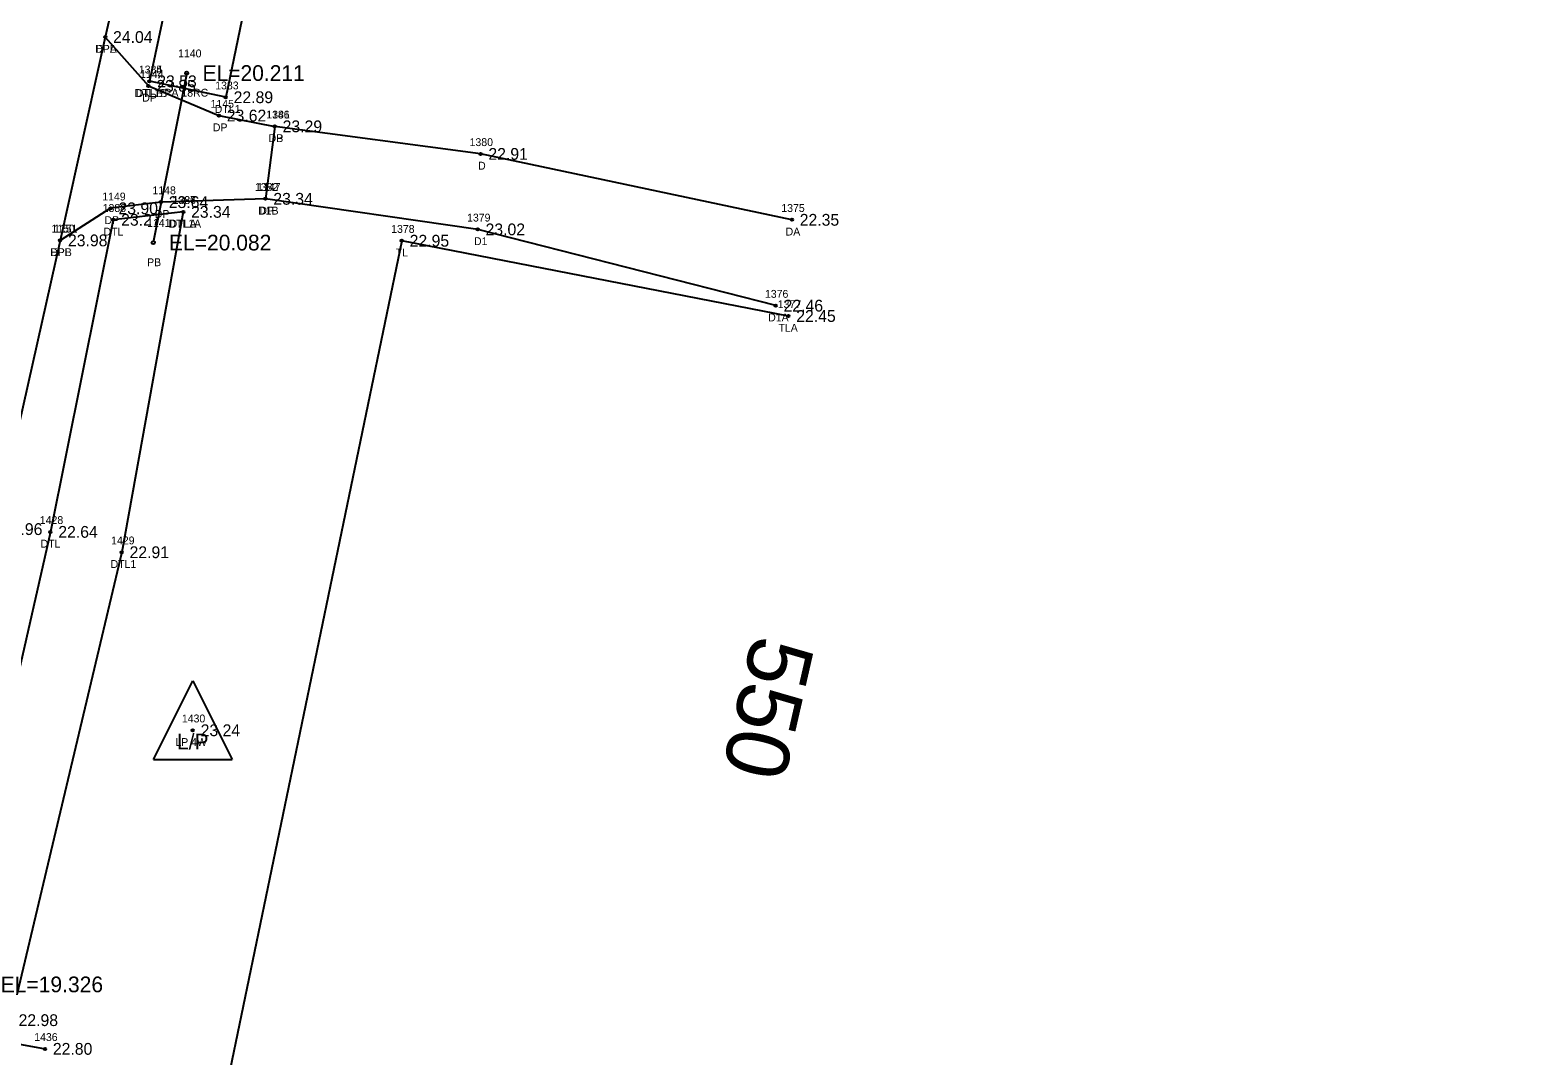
# Model space of a CAD drawing. Extents: x 2654414 to 2656963, y 761776 to 764965.
# Drawn here: x 2655871.2 to 2656062.9, y 763790 to 763920.5 of the extents above; entities that cross this region are included whole.
import ezdxf

# ---------------------------------------------------------------- set-up
doc = ezdxf.new("R2010")
doc.units = 0
for name, color, linetype in [('RD_EX_DR_Pipe', 7, 'Continuous'), ('RD_EX_DR_Pipe_txCode', 7, 'Continuous'), ('RD_EX_Driveway', 7, 'Continuous'), ('RD_EX_Driveway_txCode', 7, 'Continuous'), ('RD_EX_H2O', 7, 'Continuous'), ('RD_EX_H2O_txCode', 7, 'Continuous'), ('RD_EX_Road', 7, 'Continuous'), ('RD_EX_Road_txCode', 7, 'Continuous'), ('RD_EX_TX_Driveway_ELEV', 7, 'Continuous'), ('RD_EX_TX_H2O_ELEV', 7, 'Continuous'), ('RD_EX_TX_Road_ELEV', 7, 'Continuous'), ('RD_EX_TX_UT_ELEV', 7, 'Continuous'), ('RD_EX_TX_VEG_ELEV', 7, 'Continuous'), ('RD_EX_UT', 7, 'Continuous'), ('RD_EX_UT_txCode', 7, 'Continuous'), ('RD_EX_VEG', 7, 'Continuous'), ('RD_EX_VEG_txCode', 7, 'Continuous'), ('RD_HC_TX_Sta50', 7, 'Continuous'), ('RD_SMD_Locator', 7, 'Continuous'), ('RD_TX_Pipe_ElevEX', 7, 'Continuous')]:
    doc.layers.add(name, color=color, linetype=linetype)

msp = doc.modelspace()

# ---------------------------------------------------------------- linework, layer by layer
at = {"layer": 'RD_EX_DR_Pipe'}
msp.add_line((2655891.1, 763915.02), (2655886.84, 763893.45), dxfattribs=at)
at = {"layer": 'RD_EX_Driveway'}
for points in [[(2655880.73, 763919.6), (2655886.23, 763913.39), (2655895.19, 763909.61), (2655902.29, 763908.24), (2655901.11, 763899.02), (2655887.81, 763898.6), (2655881.42, 763897.81), (2655875, 763893.73)], [(2655968.03, 763896.35), (2655928.45, 763904.73), (2655902.29, 763908.24)], [(2655965.98, 763885.43), (2655928.09, 763895.13), (2655901.11, 763899.02)], [(2655852.89, 763796.34), (2655861.47, 763793.02), (2655873.08, 763790.88)]]:
    msp.add_lwpolyline(points, dxfattribs=at)
at = {"layer": 'RD_EX_H2O'}
msp.add_line((2655907.16, 764011.39), (2655886.35, 763913.97), dxfattribs=at)
for points in [[(2655907.16, 764011.39), (2655919.27, 764009.98), (2655903.67, 763948.66), (2655896.06, 763911.94), (2655886.35, 763913.97)], [(2655890.65, 763897.36), (2655882.83, 763854.06), (2655868.72, 763794.53), (2655860.12, 763796.62)], [(2655890.65, 763897.36), (2655881.76, 763896.35), (2655873.77, 763856.65), (2655860.12, 763796.62)]]:
    msp.add_lwpolyline(points, dxfattribs=at)
at = {"layer": 'RD_EX_Road'}
msp.add_lwpolyline([(2656062.87, 764717.57), (2656039.84, 764617.04), (2656035.41, 764597.94), (2656033.38, 764589.18), (2656018.27, 764522.6), (2656017.22, 764517.64), (2656011.07, 764490.22), (2655996.52, 764425.63), (2655974.03, 764327.02), (2655960.71, 764269.34), (2655951.96, 764231.59), (2655930.84, 764138.62), (2655926.81, 764121.01), (2655909.26, 764045.26), (2655908.15, 764039.87), (2655902.08, 764013.51), (2655888.19, 763952.26), (2655880.73, 763919.6), (2655875, 763893.73), (2655866.73, 763857), (2655852.89, 763796.34), (2655850.73, 763786.52)], dxfattribs=at)
at = {"layer": 'RD_EX_UT'}
for p, q in [((2655886.87, 763827.69), (2655891.87, 763837.69)), ((2655891.87, 763837.69), (2655896.87, 763827.69)), ((2655886.87, 763827.69), (2655896.87, 763827.69))]:
    msp.add_line(p, q, dxfattribs=at)
at = {"layer": 'RD_EX_VEG'}
msp.add_lwpolyline([(2655967.59, 763884.11), (2655918.44, 763893.69), (2655891.07, 763761.52), (2655804.95, 763371.58), (2655783.26, 763268.33)], dxfattribs=at)
at = {"layer": 'RD_SMD_Locator'}
for centre, radius in [((2655880.73, 763919.6), 0.15), ((2655880.73, 763919.6), 0.15), ((2655886.23, 763913.39), 0.15), ((2655886.35, 763913.97), 0.15), ((2655886.35, 763913.97), 0.15), ((2655891.1, 763915.02), 0.2), ((2655896.06, 763911.94), 0.15), ((2655895.19, 763909.61), 0.15), ((2655902.29, 763908.24), 0.15), ((2655902.29, 763908.24), 0.15), ((2655928.45, 763904.73), 0.15), ((2655887.81, 763898.6), 0.15), ((2655901.11, 763899.02), 0.15), ((2655901.11, 763899.02), 0.15), ((2655881.42, 763897.81), 0.15), ((2655881.76, 763896.35), 0.15), ((2655890.65, 763897.36), 0.15), ((2655890.65, 763897.36), 0.15), ((2655968.03, 763896.35), 0.15), ((2655928.09, 763895.13), 0.15), ((2655875, 763893.73), 0.15), ((2655875, 763893.73), 0.15), ((2655886.84, 763893.45), 0.2), ((2655918.44, 763893.69), 0.15), ((2655965.98, 763885.43), 0.15), ((2655967.59, 763884.11), 0.15), ((2655873.77, 763856.65), 0.15), ((2655882.83, 763854.06), 0.15), ((2655891.87, 763831.41), 0.15), ((2655873.08, 763790.88), 0.15)]:
    msp.add_circle(centre, radius, dxfattribs=at)

# ---------------------------------------------------------------- texts
at = {"layer": 'RD_EX_DR_Pipe_txCode'}
for s, p in [('1140', (2655890, 763917.02)), ('PA 18RC', (2655888.26, 763912.02)), ('1141', (2655886.06, 763895.45)), ('PB', (2655886.06, 763890.45))]:
    msp.add_text(s, height=1, dxfattribs=at).set_placement(p)
at = {"layer": 'RD_EX_Driveway_txCode'}
for s, p in [('DPA', (2655879.46, 763917.6)), ('1144', (2655885.17, 763914.39)), ('DP', (2655885.45, 763911.39)), ('1145', (2655894.13, 763910.61)), ('1146', (2655901.2, 763909.24)), ('1381', (2655901.22, 763909.24)), ('DP', (2655894.42, 763907.61)), ('DP', (2655901.51, 763906.24)), ('DB', (2655901.51, 763906.24)), ('1380', (2655927.06, 763905.73)), ('D', (2655928.14, 763902.73)), ('1148', (2655886.74, 763899.6)), ('1382', (2655899.77, 763900.02)), ('1147', (2655900.05, 763900.02)), ('1149', (2655880.36, 763898.81)), ('1375', (2655966.69, 763897.35)), ('DP', (2655880.64, 763895.81)), ('DP', (2655887.03, 763896.6)), ('D1B', (2655900.17, 763897.02)), ('DP', (2655900.33, 763897.02)), ('1379', (2655926.74, 763896.13)), ('1150', (2655873.89, 763894.73)), ('DA', (2655967.24, 763894.35)), ('DPB', (2655873.74, 763891.73)), ('D1', (2655927.62, 763893.13)), ('1376', (2655964.61, 763886.43)), ('D1A', (2655965.02, 763883.43)), ('1436', (2655871.71, 763791.88))]:
    msp.add_text(s, height=1, dxfattribs=at).set_placement(p)
at = {"layer": 'RD_EX_H2O_txCode'}
for s, p in [('1384', (2655885.01, 763914.97)), ('1385', (2655885.01, 763914.97)), ('1383', (2655894.72, 763912.94)), ('DTL1B', (2655884.47, 763911.97)), ('DTLB', (2655884.64, 763911.97)), ('DTL1', (2655894.66, 763909.94)), ('1388', (2655880.41, 763897.35)), ('1386', (2655889.28, 763898.36)), ('1387', (2655889.31, 763898.36)), ('DTL1A', (2655888.76, 763895.36)), ('DTLA', (2655888.92, 763895.36)), ('DTL', (2655880.52, 763894.35)), ('1428', (2655872.42, 763857.65)), ('1429', (2655881.49, 763855.06)), ('DTL', (2655872.52, 763854.65)), ('DTL1', (2655881.42, 763852.06))]:
    msp.add_text(s, height=1, dxfattribs=at).set_placement(p)
at = {"layer": 'RD_EX_Road_txCode'}
for s, p in [('EPL', (2655879.52, 763917.6)), ('1151', (2655874.22, 763894.73)), ('EPL', (2655873.79, 763891.73))]:
    msp.add_text(s, height=1, dxfattribs=at).set_placement(p)
at = {"layer": 'RD_EX_TX_Driveway_ELEV'}
for s, p in [('24.04', (2655881.73, 763918.85)), ('23.85', (2655887.23, 763912.64)), ('23.62', (2655896.19, 763908.86)), ('23.29', (2655903.29, 763907.49)), ('23.29', (2655903.29, 763907.49)), ('22.91', (2655929.45, 763903.98)), ('23.90', (2655882.42, 763897.06)), ('23.64', (2655888.81, 763897.85)), ('23.34', (2655902.11, 763898.27)), ('23.34', (2655902.11, 763898.27)), ('22.35', (2655969.03, 763895.6)), ('23.98', (2655876, 763892.98)), ('23.02', (2655929.09, 763894.38)), ('22.46', (2655966.98, 763884.68)), ('22.80', (2655874.08, 763790.13))]:
    msp.add_text(s, height=1.5, dxfattribs=at).set_placement(p)
at = {"layer": 'RD_EX_TX_H2O_ELEV'}
for s, p in [('23.53', (2655887.35, 763913.22)), ('23.53', (2655887.35, 763913.22)), ('22.89', (2655897.06, 763911.19)), ('23.34', (2655891.65, 763896.61)), ('23.34', (2655891.65, 763896.61)), ('23.27', (2655882.76, 763895.6)), ('22.64', (2655874.77, 763855.9)), ('22.91', (2655883.83, 763853.31)), ('22.98', (2655869.72, 763793.78))]:
    msp.add_text(s, height=1.5, dxfattribs=at).set_placement(p)
at = {"layer": 'RD_EX_TX_Road_ELEV'}
for s, p in [('24.04', (2655881.73, 763918.85)), ('23.98', (2655876, 763892.98)), ('23.96', (2655867.73, 763856.25))]:
    msp.add_text(s, height=1.5, dxfattribs=at).set_placement(p)
at = {"layer": 'RD_EX_TX_UT_ELEV'}
msp.add_text('23.24', height=1.5, dxfattribs=at).set_placement((2655892.87, 763830.66))
at = {"layer": 'RD_EX_TX_VEG_ELEV'}
for s, p in [('22.95', (2655919.44, 763892.94)), ('22.45', (2655968.59, 763883.36))]:
    msp.add_text(s, height=1.5, dxfattribs=at).set_placement(p)
at = {"layer": 'RD_EX_UT'}
msp.add_text('L/P', height=2, dxfattribs=at).set_placement((2655889.86, 763828.97))
at = {"layer": 'RD_EX_UT_txCode'}
for s, p in [('1430', (2655890.48, 763832.41)), ('LP 4W', (2655889.65, 763829.41))]:
    msp.add_text(s, height=1, dxfattribs=at).set_placement(p)
at = {"layer": 'RD_EX_VEG_txCode'}
for s, p in [('1378', (2655917.09, 763894.69)), ('TL', (2655917.67, 763891.69)), ('1377', (2655966.24, 763885.11)), ('TLA', (2655966.33, 763882.11))]:
    msp.add_text(s, height=1, dxfattribs=at).set_placement(p)
at = {"layer": 'RD_HC_TX_Sta50'}
msp.add_text('550', height=8, rotation=257.149, dxfattribs=at).set_placement((2655963.13, 763843.78))
at = {"layer": 'RD_TX_Pipe_ElevEX'}
for s, p in [('EL=20.211', (2655893.1, 763914.02)), ('EL=20.082', (2655888.84, 763892.45)), ('EL=19.326', (2655867.45, 763798.08))]:
    msp.add_text(s, height=2, dxfattribs=at).set_placement(p)

doc.saveas('drawing.dxf')
